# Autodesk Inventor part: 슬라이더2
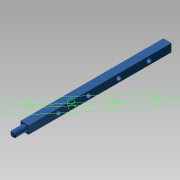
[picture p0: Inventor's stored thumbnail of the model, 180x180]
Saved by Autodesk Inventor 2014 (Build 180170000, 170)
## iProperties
Company: 한국ATC센터
Created: 2015-04
Part Number: 슬라이더2
Document SubType Name: Modeling
Designer: KYOUNG IL JANG
Density: 7.85 g/cm^3
Material: 강
Mass: 69.0062 g
Surface Area: 52.3143 cm^2
Volume: 8.7906 cm^3
Appearance: 하늘색 짙음
Author: KYOUNG IL JANG
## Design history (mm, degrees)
sketch "스케치3"
  geometry: L1 (4, 142)-(-4, 142); L2 (-4, 142)-(-4, 0); L3 (-4, 0)-(4, 0); L4 (4, 0)-(4, 142); 3 further points
  constraints: 8 end point, 2 coincident, 2 parallel, 1 horizontal, 1 midpoint, 1 perpendicular
  dimensions: "d5" = 8 distance of L1.start L1.end; "d6" = 142 distance of L1.end L2.end
extrude "돌출3" new body sketch "스케치3" stored distance "d7" = 8; taper "d8" = 0 deg
sketch "스케치4"
  geometry: L1 (8, 0)-(0, 0) reference; 3 further points
  constraints: 1 midpoint, 1 vertical alignment
  dimensions: "d9" = 30 distance of point (4, 30) point (4, 0)
hole "구멍1" sketch "스케치4" at (4, 30) diameter "d10" = 5; stored, may be unused: countersink angle "d14" = 90 deg, drill point angle "d16" = 118 deg; dims "d11" = 6, "d12" = 4, "d13" = 2, "d15" = 8
sketch "스케치5"
  geometry: C1 r 3 at (4, -4); 1 further point
  constraints: 1 centre point, 1 coincident
  dimensions: "d20" = 6 diameter of C1
extrude "돌출4" join sketch "스케치5" distance "d21" = 12; taper "d22" = 0 deg
chamfer "모따기1" distance "d23" = 1; stored, may be unused: second distance "d24" = 2, angle "d25" = 45 deg
node "작업 평면2"
  node "작업축1"
node "솔리드1"
pattern_linear "직사각형 패턴1" dims "d19" = 30
node "솔리드2"
other parameters: "d26" = 0
